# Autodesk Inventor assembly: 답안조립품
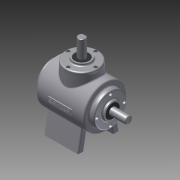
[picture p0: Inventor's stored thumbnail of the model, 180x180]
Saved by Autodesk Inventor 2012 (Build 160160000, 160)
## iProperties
Created: 2015-01
Part Number: 답안조립품
Document SubType Name: Assembly
Designer: Owner
Author: Owner
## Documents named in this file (14)
- C:\Documents and Settings\Owner\바탕 화면\450105V1012\답안조립품.iam
- C:\Documents and Settings\Owner\바탕 화면\450105V1012\1 본체.ipt
- C:\Documents and Settings\Owner\바탕 화면\450105V1012\오일실.ipt
- C:\Documents and Settings\Owner\바탕 화면\450105V1012\베어링 6203.ipt
- C:\Documents and Settings\Owner\바탕 화면\450105V1012\커버.ipt
- C:\Documents and Settings\Owner\바탕 화면\450105V1012\서브 축.ipt
- 서브 축.ipt
- C:\Documents and Settings\Owner\바탕 화면\450105V1012\서브 베벨기어.ipt
- C:\Documents and Settings\Owner\바탕 화면\450105V1012\키 4x4.ipt
- C:\Documents and Settings\Owner\바탕 화면\450105V1012\커버2.ipt
- C:\Documents and Settings\Owner\바탕 화면\450105V1012\메인 베벨기어.ipt
- C:\Documents and Settings\Owner\바탕 화면\450105V1012\메인 축.ipt
- 메인 축.ipt
- C:\Documents and Settings\Owner\바탕 화면\450105V1012\키 5x5.ipt
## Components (1 placed, 1 different names)
1. 1 본체:1
